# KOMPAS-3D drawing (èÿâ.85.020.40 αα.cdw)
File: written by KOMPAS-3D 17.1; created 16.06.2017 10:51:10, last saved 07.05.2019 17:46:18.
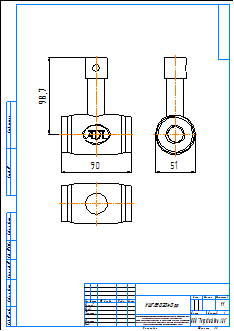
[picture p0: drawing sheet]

Sheet 1: A3, portrait

Title block, sheet 1: name: КШГ.85.020.40 рр; material: Внимание! Данный продукт является объектом авторского права ООО «Торговый Дом АДЛ». / Запрещается изменение, копирование, распространение / (в том числе путем копирования на другие сайты и ресурсы в Интернете) / или любое иное использование информации и объектов без предварительного / согласия правообладателя (ООО «Торговый Дом АДЛ»).; scale: 1:1; sheets: 1; organisation: ООО "Торговый дом АДЛ"; sheet format: A3; stored path: C:\Users\tra\Desktop\2д чертежи\Шаровые краны БИВАЛ\КШ_Бивал_серия_82_85\KOMPAS 2D\КШГ.85.020.40 рр.cdw

Views: Спереди 1, Проекционный вид 2, Проекционный вид 3
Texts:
  Klimkovich
  ADL
Dimensions and other numbers on the sheet: 90; 98,7; 51; 1:1; 1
